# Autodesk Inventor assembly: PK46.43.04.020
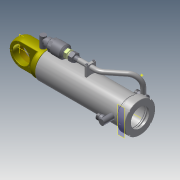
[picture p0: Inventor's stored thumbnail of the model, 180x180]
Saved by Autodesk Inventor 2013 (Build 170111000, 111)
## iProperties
Shininess: 64.0
Length Units: 11269
Angle Units: 11279
Time Units: 11290
Mass Units: 11283
Length Display Precision: 3
Angle Display Precision: 2
Compacted: True
Created: 2004-11
Part Number: PK46.43.04.020
Document SubType Name: Assembly
Designer: ELarisa
Manufacturer: Standard
Standards Organization: Custom
Density: 0.0
Volumn: 0.0
Area: 0.0
PropertySet Name: Model Information
Control State: 0
Master: False
Checked Out: False
Author: ELarisa
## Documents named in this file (12)
- D:\FrontLoaderVault\Data\Assy, Chassis, Front\PK46.43.04.020.iam
- D:\FrontLoaderVault\Data\Assy, Chassis, Front\PK46.43.02.002.ipt
- D:\FrontLoaderVault\Data\Assy, Chassis, Front\PK46.43.02.007.ipt
- D:\FrontLoaderVault\Data\Assy, Chassis, Front\PK46.43.02.015.ipt
- D:\FrontLoaderVault\Data\Assy, Chassis, Front\PK46.43.02.006.ipt
- D:\FrontLoaderVault\Data\Assy, Chassis, Front\027.01.01.550.iam
- D:\FrontLoaderVault\Data\Assy, Chassis, Front\PK46.43.02.040.iam
- D:\FrontLoaderVault\Data\Assy, Chassis, Front\PK46.43.02.016.ipt
- D:\FrontLoaderVault\Data\Assy, Chassis, Front\62900A.ipt
- D:\FrontLoaderVault\Data\Assy, Chassis, Front\8.65G.019.ipt
- D:\FrontLoaderVault\Data\Assy, Chassis, Front\PK46.43.00.008.ipt
- D:\FrontLoaderVault\Data\Assy, Chassis, Front\M8-6gx50.58.019(S13).ipt
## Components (14 placed, 11 different names)
1. PK46.43.02.002:1 — Insert:1, Angle:1, Angle:3, Insert:16, Insert:19
2. PK46.43.02.007:1 — Insert:1, Angle:1, Angle:2, Insert:4
3. PK46.43.02.015:1 — Angle:2, Insert:5, Insert:8
4. 027.01.01.550:1 [sub-assembly] — Insert:4, Angle:3, Insert:13, Angle:4
5. PK46.43.02.040:1 [sub-assembly] — Insert:15
6. PK46.43.02.016:1 — Insert:5, Insert:6, Insert:7, Insert:8
7. 8.65G.019:1 — Insert:6, Insert:10
8. 8.65G.019:2 — Insert:7, Insert:9
9. M8-6gx50.58.019(S13):1 — Insert:10
10. M8-6gx50.58.019(S13):2 — Insert:9
11. 62900A:1 — Insert:13, Insert:14
12. PK46.43.00.008:1 — Insert:14, Insert:15
13. 027.01.01.550:2 [sub-assembly] — Insert:16, Angle:4
14. PK46.43.02.006:1 — Insert:19
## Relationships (17: Insert 13, Angle 4)
- Insert:1: PK46.43.02.002:1 ↔ PK46.43.02.007:1
- Angle:1: PK46.43.02.002:1 ↔ PK46.43.02.007:1
- Angle:2: PK46.43.02.007:1 ↔ PK46.43.02.015:1
- Insert:4: PK46.43.02.007:1 ↔ 027.01.01.550:1
- Angle:3: PK46.43.02.002:1 ↔ 027.01.01.550:1
- Insert:5: PK46.43.02.015:1 ↔ PK46.43.02.016:1
- Insert:6: PK46.43.02.016:1 ↔ 8.65G.019:1
- Insert:7: PK46.43.02.016:1 ↔ 8.65G.019:2
- Insert:8: PK46.43.02.015:1 ↔ PK46.43.02.016:1
- Insert:9: 8.65G.019:2 ↔ M8-6gx50.58.019(S13):2
- Insert:10: 8.65G.019:1 ↔ M8-6gx50.58.019(S13):1
- Insert:13: 027.01.01.550:1 ↔ 62900A:1
- Insert:14: 62900A:1 ↔ PK46.43.00.008:1
- Insert:15: PK46.43.02.040:1 ↔ PK46.43.00.008:1
- Insert:16: PK46.43.02.002:1 ↔ 027.01.01.550:2
- Angle:4: 027.01.01.550:1 ↔ 027.01.01.550:2
- Insert:19: PK46.43.02.002:1 ↔ PK46.43.02.006:1
